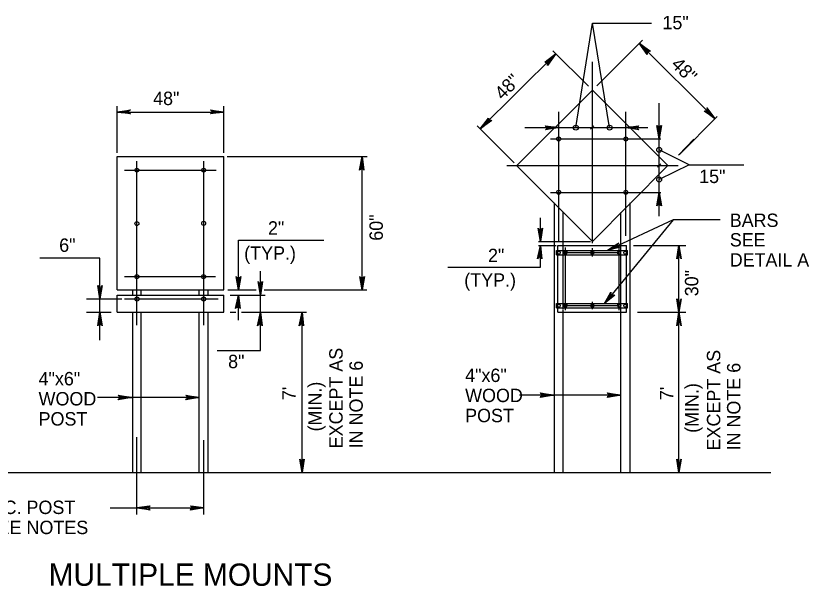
# Model space of a CAD drawing. Extents: x 648590 to 650336, y 294467 to 295061.
# Drawn here: x 648999.2 to 649176.8, y 294775 to 294902.8 of the extents above; entities that cross this region are included whole.
import ezdxf

# ---------------------------------------------------------------- set-up
doc = ezdxf.new("R2010")
doc.units = 0
doc.layers.add('2', color=7, linetype='Continuous')
doc.layers.add('3', color=7, linetype='Continuous')

msp = doc.modelspace()

# ---------------------------------------------------------------- linework, layer by layer
at = {"layer": '2'}
for p, q in [((649124.59, 294877.74), (649128.28, 294901.12)), ((649128.28, 294901.12), (649141.54, 294901.12)), ((649139.51, 294897.35), (649129.28, 294887.12)), ((649155.68, 294879.77), (649138.8, 294896.64)), ((649119.46, 294894.94), (649127.4, 294886.99)), ((649103.18, 294877.47), (649120, 294894.17)), ((649128.28, 294851.87), (649128.28, 294892.49)), ((649111.4, 294869.24), (649128.28, 294886.12)), ((649145.15, 294869.24), (649128.28, 294886.12)), ((649021.91, 294872.12), (649021.91, 294882.56)), ((649045.79, 294872.12), (649045.79, 294882.56)), ((649143.24, 294857.88), (649143.24, 294883.22)), ((649021.91, 294881.22), (649045.79, 294881.22)), ((649120.78, 294852.24), (649120.78, 294881.24)), ((649135.78, 294853.49), (649135.78, 294881.24)), ((649156.26, 294880.23), (649147.78, 294871.75)), ((649110.78, 294869.87), (649102.52, 294878.13)), ((649113.18, 294877.74), (649128.28, 294877.74)), ((649117.15, 294877.74), (649128.28, 294877.74)), ((649127.9, 294877.37), (649128.65, 294878.12)), ((649128.28, 294877.74), (649139.4, 294877.74)), ((649128.28, 294877.74), (649140.67, 294877.74)), ((649118.9, 294875.24), (649143.65, 294875.24)), ((649119.03, 294875.24), (649143.65, 294875.24)), ((649151.03, 294875.12), (649147.58, 294871.59)), ((649021.91, 294841.37), (649021.91, 294871.24)), ((649021.91, 294871.24), (649045.79, 294871.24)), ((649045.79, 294841.37), (649045.79, 294871.24)), ((649046.54, 294871.24), (649077.88, 294871.24)), ((649076.76, 294841.37), (649076.76, 294871.24)), ((649149.98, 294869.42), (649143.24, 294872.77)), ((649026.29, 294833.49), (649026.29, 294870.21)), ((649041.29, 294833.49), (649041.29, 294870.21)), ((649142.87, 294868.87), (649143.62, 294869.62)), ((649149.98, 294869.42), (649143.24, 294866.1)), ((649149.98, 294869.42), (649162.22, 294869.42)), ((649023.54, 294868.24), (649044.04, 294868.24)), ((649026.29, 294868.24), (649026.29, 294868.24)), ((649041.29, 294868.24), (649041.29, 294868.24)), ((649109.15, 294869.24), (649147.53, 294869.24)), ((649109.15, 294869.24), (649147.53, 294869.24)), ((649128.28, 294852.24), (649111.28, 294869.24)), ((649128.28, 294852.24), (649145.15, 294869.24)), ((649118.9, 294863.24), (649143.65, 294863.24)), ((649119.03, 294863.24), (649143.65, 294863.24)), ((649119.78, 294800.49), (649119.78, 294860.87)), ((649136.78, 294800.49), (649136.78, 294860.87)), ((649116.64, 294852.24), (649116.64, 294857.57)), ((649121.78, 294851.87), (649121.78, 294858.74)), ((649134.65, 294851.87), (649134.65, 294858.74)), ((649026.29, 294856.24), (649026.29, 294856.24)), ((649041.29, 294856.24), (649041.29, 294856.24)), ((649049.05, 294841.37), (649049.05, 294852.5)), ((649049.05, 294852.5), (649068.2, 294852.5)), ((649116.22, 294852.24), (649127.9, 294852.24)), ((649121.78, 294836.99), (649121.78, 294851.87)), ((649134.65, 294836.87), (649134.65, 294851.87)), ((649116.25, 294851.37), (649120.15, 294851.37)), ((649116.64, 294846.5), (649116.64, 294851.37)), ((649120.28, 294849.24), (649120.28, 294850.24)), ((649120.28, 294850.24), (649121.37, 294850.24)), ((649120.53, 294836.37), (649120.53, 294851.37)), ((649120.53, 294851.37), (649135.9, 294851.37)), ((649121.37, 294850.24), (649135.28, 294850.24)), ((649122.28, 294836.87), (649122.28, 294850.87)), ((649128.29, 294848.84), (649128.29, 294850.72)), ((649134.28, 294836.87), (649134.28, 294850.87)), ((649135.28, 294850.24), (649136.15, 294850.24)), ((649135.9, 294836.37), (649135.9, 294851.37)), ((649136.15, 294849.24), (649136.15, 294850.24)), ((649137.53, 294851.37), (649149.18, 294851.37)), ((649147.68, 294836.37), (649147.68, 294851.37)), ((649018.04, 294848.5), (649004.59, 294848.5)), ((649018.04, 294839.37), (649018.04, 294848.5)), ((649120.28, 294849.24), (649121.37, 294849.24)), ((649121.37, 294849.24), (649135.28, 294849.24)), ((649122.28, 294849.74), (649134.28, 294849.74)), ((649135.28, 294849.24), (649136.15, 294849.24)), ((649095.96, 294846.5), (649116.64, 294846.5)), ((649053.96, 294840.24), (649053.96, 294845.57)), ((649023.54, 294844.37), (649043.91, 294844.37)), ((649026.29, 294844.37), (649026.29, 294844.37)), ((649041.29, 294844.37), (649041.29, 294844.37)), ((649021.91, 294841.37), (649045.79, 294841.37)), ((649025.41, 294840.24), (649025.41, 294841.37)), ((649027.29, 294840.24), (649027.29, 294841.37)), ((649040.29, 294840.24), (649040.29, 294841.37)), ((649042.29, 294840.24), (649042.29, 294841.37)), ((649046.66, 294841.37), (649053.01, 294841.37)), ((649054.82, 294841.37), (649077.76, 294841.37)), ((649015.04, 294839.37), (649022.91, 294839.37)), ((649018.04, 294830.12), (649018.04, 294839.37)), ((649021.91, 294840.24), (649045.79, 294840.24)), ((649021.91, 294836.37), (649021.91, 294840.24)), ((649023.54, 294839.37), (649044.54, 294839.37)), ((649026.29, 294839.37), (649026.29, 294839.37)), ((649041.29, 294839.37), (649041.29, 294839.37)), ((649045.79, 294836.37), (649045.79, 294840.24)), ((649047.16, 294840.24), (649055.06, 294840.24)), ((649049.05, 294834.61), (649049.05, 294840.24)), ((649053.96, 294827.79), (649053.96, 294840.24)), ((649120.28, 294837.37), (649120.28, 294838.37)), ((649120.28, 294838.37), (649121.37, 294838.37)), ((649121.37, 294838.37), (649135.12, 294838.37)), ((649122.28, 294837.87), (649134.28, 294837.87)), ((649128.29, 294837.09), (649128.29, 294838.75)), ((649135.12, 294838.37), (649136.15, 294838.37)), ((649136.15, 294837.37), (649136.15, 294838.37)), ((649015.04, 294836.37), (649020.54, 294836.37)), ((649021.91, 294836.37), (649045.79, 294836.37)), ((649025.41, 294800.49), (649025.41, 294836.37)), ((649027.29, 294800.49), (649027.29, 294836.37)), ((649040.29, 294800.49), (649040.29, 294836.37)), ((649042.29, 294800.49), (649042.29, 294836.37)), ((649047.16, 294836.37), (649048.44, 294836.37)), ((649049.76, 294836.37), (649064.28, 294836.37)), ((649063.28, 294800.49), (649063.28, 294836.37)), ((649120.28, 294837.37), (649121.37, 294837.37)), ((649120.53, 294836.37), (649135.9, 294836.37)), ((649121.37, 294837.37), (649135.12, 294837.37)), ((649121.78, 294800.49), (649121.78, 294836.87)), ((649134.65, 294800.49), (649134.65, 294836.87)), ((649135.12, 294837.37), (649136.15, 294837.37)), ((649138.4, 294836.37), (649149.18, 294836.37)), ((649147.68, 294800.49), (649147.68, 294836.37)), ((649044.31, 294827.79), (649053.96, 294827.79)), ((649040.29, 294817.29), (649017.48, 294817.29)), ((649134.65, 294817.82), (649111.97, 294817.82)), ((649026.29, 294791.08), (649026.29, 294808.37)), ((649041.29, 294791.08), (649041.29, 294807.74)), ((648903.79, 294800.49), (649168.28, 294800.49)), ((649020.36, 294792.58), (649041.29, 294792.58))]:
    msp.add_line(p, q, dxfattribs=at)
for points in [[(649132.15, 294877.74), (649128.28, 294901.12)], [(649140.55, 294894.39), (649140.68, 294894.64), (649138.8, 294896.64), (649140.55, 294894.39), (649140.55, 294894.14), (649138.8, 294896.64), (649140.8, 294894.77), (649141.05, 294894.89), (649138.8, 294896.64), (649141.3, 294894.89), (649141.05, 294894.89)], [(649117.75, 294892.42), (649117.88, 294892.42), (649120, 294894.17), (649117.75, 294892.42), (649117.63, 294892.42), (649120, 294894.17), (649118.13, 294892.17), (649118.25, 294891.92), (649120, 294894.17), (649118.25, 294891.67), (649118.25, 294891.92)], [(649154.05, 294881.89), (649153.93, 294881.77), (649155.68, 294879.77), (649154.05, 294881.89), (649153.93, 294882.14), (649155.68, 294879.77), (649153.68, 294881.52), (649153.55, 294881.39), (649155.68, 294879.77), (649153.3, 294881.39), (649153.55, 294881.39)], [(649024.66, 294880.97), (649024.66, 294881.1), (649021.91, 294881.22), (649024.66, 294880.97), (649024.91, 294880.85), (649021.91, 294881.22), (649024.54, 294881.47), (649024.66, 294881.6), (649021.91, 294881.22), (649024.91, 294881.72), (649024.66, 294881.6)], [(649042.91, 294881.6), (649043.04, 294881.47), (649045.79, 294881.22), (649042.91, 294881.6), (649042.79, 294881.72), (649045.79, 294881.22), (649043.04, 294881.1), (649042.91, 294880.97), (649045.79, 294881.22), (649042.79, 294880.85), (649042.91, 294880.97)], [(649105.55, 294879.34), (649105.3, 294879.34), (649103.18, 294877.47), (649105.55, 294879.34), (649105.8, 294879.34), (649103.18, 294877.47), (649105.18, 294879.47), (649105.05, 294879.72), (649103.18, 294877.47), (649105.05, 294879.84), (649105.05, 294879.72)], [(649117.89, 294877.99), (649118.02, 294877.87), (649120.77, 294877.74), (649117.89, 294877.99), (649117.77, 294878.12), (649120.77, 294877.74), (649118.02, 294877.62), (649118.02, 294877.49), (649120.77, 294877.74), (649117.77, 294877.24), (649118.02, 294877.49)], [(649138.53, 294877.37), (649138.4, 294877.62), (649135.78, 294877.74), (649138.53, 294877.37), (649138.65, 294877.24), (649135.78, 294877.74), (649138.4, 294877.74), (649138.53, 294877.99), (649135.78, 294877.74), (649138.65, 294878.12), (649138.53, 294877.99)], [(649143.62, 294878.12), (649143.37, 294877.99), (649143.24, 294875.24), (649143.62, 294878.12), (649143.74, 294878.24), (649143.24, 294875.24), (649142.99, 294877.99), (649142.87, 294878.12), (649143.24, 294875.24), (649142.74, 294878.24), (649142.87, 294878.12)], [(649076.38, 294868.37), (649076.51, 294868.49), (649076.76, 294871.24), (649076.38, 294868.37), (649076.13, 294868.24), (649076.76, 294871.24), (649076.88, 294868.49), (649077.01, 294868.37), (649076.76, 294871.24), (649077.13, 294868.24), (649077.01, 294868.37)], [(649142.87, 294860.37), (649142.99, 294860.49), (649143.24, 294863.24), (649142.87, 294860.37), (649142.74, 294860.24), (649143.24, 294863.24), (649143.37, 294860.49), (649143.49, 294860.37), (649143.24, 294863.24), (649143.74, 294860.24), (649143.49, 294860.37)], [(649156.88, 294857.12), (649146.4, 294857.12), (649131.03, 294838.37)], [(649146.4, 294857.12), (649131.65, 294850.24)], [(649116.89, 294854.99), (649116.76, 294854.99), (649116.64, 294852.24), (649116.89, 294854.99), (649117.14, 294855.24), (649116.64, 294852.24), (649116.39, 294854.99), (649116.26, 294854.99), (649116.64, 294852.24), (649116.14, 294855.24), (649116.26, 294854.99)], [(649134.27, 294851.12), (649134.22, 294851.24), (649131.65, 294850.24), (649134.27, 294851.12), (649134.6, 294850.99), (649131.65, 294850.24), (649134.07, 294851.58), (649134.02, 294851.69), (649131.65, 294850.24), (649134.2, 294851.91), (649134.02, 294851.69)], [(649116.26, 294848.62), (649116.39, 294848.62), (649116.64, 294851.37), (649116.26, 294848.62), (649116.01, 294848.37), (649116.64, 294851.37), (649116.76, 294848.62), (649116.89, 294848.62), (649116.64, 294851.37), (649117.01, 294848.37), (649116.89, 294848.62)], [(649147.31, 294848.49), (649147.56, 294848.62), (649147.68, 294851.37), (649147.31, 294848.49), (649147.18, 294848.37), (649147.68, 294851.37), (649147.93, 294848.62), (649148.06, 294848.49), (649147.68, 294851.37), (649148.18, 294848.37), (649148.06, 294848.49)], [(649049.3, 294844.12), (649049.17, 294844.12), (649049.05, 294841.37), (649049.3, 294844.12), (649049.55, 294844.37), (649049.05, 294841.37), (649048.8, 294844.12), (649048.67, 294844.12), (649049.05, 294841.37), (649048.55, 294844.37), (649048.67, 294844.12)], [(649054.21, 294842.99), (649054.08, 294842.99), (649053.96, 294840.24), (649054.21, 294842.99), (649054.46, 294843.24), (649053.96, 294840.24), (649053.71, 294842.99), (649053.58, 294842.99), (649053.96, 294840.24), (649053.46, 294843.24), (649053.58, 294842.99)], [(649077.01, 294844.12), (649076.88, 294844.12), (649076.76, 294841.37), (649077.01, 294844.12), (649077.26, 294844.37), (649076.76, 294841.37), (649076.51, 294844.12), (649076.38, 294844.12), (649076.76, 294841.37), (649076.26, 294844.37), (649076.38, 294844.12)], [(649018.41, 294842.24), (649018.29, 294842.12), (649018.04, 294839.37), (649018.41, 294842.24), (649018.54, 294842.37), (649018.04, 294839.37), (649017.91, 294842.12), (649017.79, 294842.24), (649018.04, 294839.37), (649017.54, 294842.37), (649017.79, 294842.24)], [(649048.67, 294837.49), (649048.8, 294837.49), (649049.05, 294840.24), (649048.67, 294837.49), (649048.42, 294837.24), (649049.05, 294840.24), (649049.17, 294837.49), (649049.3, 294837.49), (649049.05, 294840.24), (649049.42, 294837.24), (649049.3, 294837.49)], [(649148.06, 294839.24), (649147.93, 294839.12), (649147.68, 294836.37), (649148.06, 294839.24), (649148.18, 294839.37), (649147.68, 294836.37), (649147.56, 294839.12), (649147.43, 294839.24), (649147.68, 294836.37), (649147.18, 294839.37), (649147.43, 294839.24)], [(649017.66, 294833.62), (649017.91, 294833.62), (649018.04, 294836.37), (649017.66, 294833.62), (649017.54, 294833.37), (649018.04, 294836.37), (649018.16, 294833.62), (649018.41, 294833.62), (649018.04, 294836.37), (649018.54, 294833.37), (649018.41, 294833.62)], [(649053.58, 294833.62), (649053.71, 294833.62), (649053.96, 294836.37), (649053.58, 294833.62), (649053.33, 294833.37), (649053.96, 294836.37), (649054.08, 294833.62), (649054.21, 294833.62), (649053.96, 294836.37), (649054.33, 294833.37), (649054.21, 294833.62)], [(649062.9, 294833.62), (649063.03, 294833.62), (649063.28, 294836.37), (649062.9, 294833.62), (649062.65, 294833.37), (649063.28, 294836.37), (649063.4, 294833.62), (649063.53, 294833.62), (649063.28, 294836.37), (649063.65, 294833.37), (649063.53, 294833.62)], [(649147.31, 294833.62), (649147.56, 294833.62), (649147.68, 294836.37), (649147.31, 294833.62), (649147.18, 294833.37), (649147.68, 294836.37), (649147.93, 294833.62), (649148.06, 294833.62), (649147.68, 294836.37), (649148.18, 294833.37), (649148.06, 294833.62)], [(649116.77, 294818.2), (649116.89, 294818.07), (649119.64, 294817.82), (649116.77, 294818.2), (649116.64, 294818.32), (649119.64, 294817.82), (649116.89, 294817.7), (649116.77, 294817.57), (649119.64, 294817.82), (649116.64, 294817.32), (649116.77, 294817.57)], [(649131.78, 294818.2), (649131.9, 294818.07), (649134.65, 294817.82), (649131.78, 294818.2), (649131.65, 294818.32), (649134.65, 294817.82), (649131.9, 294817.7), (649131.78, 294817.57), (649134.65, 294817.82), (649131.65, 294817.32), (649131.78, 294817.57)], [(649022.28, 294817.66), (649022.4, 294817.54), (649025.15, 294817.29), (649022.28, 294817.66), (649022.15, 294817.79), (649025.15, 294817.29), (649022.4, 294817.16), (649022.28, 294817.04), (649025.15, 294817.29), (649022.15, 294816.79), (649022.28, 294817.04)], [(649037.41, 294817.66), (649037.54, 294817.54), (649040.29, 294817.29), (649037.41, 294817.66), (649037.29, 294817.79), (649040.29, 294817.29), (649037.54, 294817.16), (649037.41, 294817.04), (649040.29, 294817.29), (649037.29, 294816.79), (649037.41, 294817.04)], [(649063.53, 294803.37), (649063.4, 294803.24), (649063.28, 294800.49), (649063.53, 294803.37), (649063.78, 294803.49), (649063.28, 294800.49), (649063.03, 294803.24), (649062.9, 294803.37), (649063.28, 294800.49), (649062.78, 294803.49), (649062.9, 294803.37)], [(649148.06, 294803.37), (649147.93, 294803.24), (649147.68, 294800.49), (649148.06, 294803.37), (649148.18, 294803.49), (649147.68, 294800.49), (649147.56, 294803.24), (649147.43, 294803.37), (649147.68, 294800.49), (649147.18, 294803.49), (649147.43, 294803.37)], [(649029.16, 294792.21), (649029.04, 294792.46), (649026.29, 294792.58), (649029.16, 294792.21), (649029.29, 294792.08), (649026.29, 294792.58), (649029.04, 294792.83), (649029.16, 294792.96), (649026.29, 294792.58), (649029.29, 294792.96), (649029.16, 294792.96)], [(649038.41, 294792.96), (649038.54, 294792.83), (649041.29, 294792.58), (649038.41, 294792.96), (649038.29, 294792.96), (649041.29, 294792.58), (649038.54, 294792.46), (649038.41, 294792.33), (649041.29, 294792.58), (649038.29, 294792.08), (649038.41, 294792.33)]]:
    msp.add_lwpolyline(points, dxfattribs=at)
for centre, radius in [((649124.59, 294877.74), 0.55), ((649132.15, 294877.74), 0.55), ((649120.75, 294875.21), 0.441), ((649135.78, 294875.19), 0.441), ((649143.24, 294872.77), 0.55), ((649026.31, 294868.21), 0.441), ((649041.26, 294868.21), 0.441), ((649143.24, 294866.1), 0.55), ((649120.75, 294863.26), 0.441), ((649135.78, 294863.25), 0.441), ((649026.31, 294856.24), 0.441), ((649041.26, 294856.31), 0.441), ((649120.76, 294849.74), 0.35), ((649122.28, 294849.74), 0.35), ((649128.27, 294849.74), 0.35), ((649134.25, 294849.74), 0.35), ((649135.68, 294849.74), 0.35), ((649026.31, 294844.35), 0.441), ((649041.23, 294844.35), 0.441), ((649026.33, 294839.34), 0.441), ((649041.25, 294839.34), 0.441), ((649120.76, 294837.87), 0.35), ((649122.28, 294837.87), 0.35), ((649128.29, 294837.87), 0.35), ((649134.28, 294837.87), 0.35), ((649135.67, 294837.87), 0.35)]:
    msp.add_circle(centre, radius, dxfattribs=at)
at = {"layer": '3'}
for p, q in [((649120.78, 294875.24), (649120.78, 294875.24)), ((649120.9, 294875.24), (649120.9, 294875.24)), ((649135.78, 294875.24), (649135.78, 294875.24)), ((649135.78, 294875.24), (649135.78, 294875.24)), ((649120.78, 294863.24), (649120.78, 294863.24)), ((649120.9, 294863.24), (649120.9, 294863.24)), ((649135.78, 294863.24), (649135.78, 294863.24)), ((649135.78, 294863.24), (649135.78, 294863.24))]:
    msp.add_line(p, q, dxfattribs=at)
msp.add_lwpolyline([(649133.03, 294840.24), (649132.78, 294840.24), (649131.03, 294838.37), (649133.03, 294840.24), (649133.28, 294840.24), (649131.03, 294838.37), (649132.53, 294840.49), (649132.4, 294840.74), (649131.03, 294838.37), (649132.4, 294840.87), (649132.4, 294840.74)], dxfattribs=at)

# ---------------------------------------------------------------- texts
at = {"layer": '2'}
msp.add_text('MULTIPLE MOUNTS', height=5, dxfattribs=at).set_placement((649006.55, 294775.11))
at = {"layer": '3'}
for s, height, p in [('15"', 3, (649143.97, 294899.77)), ('48"', 3, (649029.94, 294882.79)), ('15"', 3, (649152.19, 294865.32)), ('BARS', 2.988, (649159.06, 294855.49)), ('2"', 3, (649055.66, 294853.76)), ('SEE', 2.988, (649159.06, 294851.12)), ('6"', 3, (649008.91, 294849.91)), ('(TYP.)', 3, (649050.33, 294848.13)), ('2"', 3, (649104.92, 294847.61)), ('DETAIL A', 2.988, (649159.06, 294846.62)), ('(TYP.)', 3, (649099.6, 294842.1)), ('8"', 3, (649046.73, 294823.86)), ('4"x6"', 3, (649099.8, 294820.76)), ('4"x6"', 3, (649004.3, 294820.01)), ('WOOD', 3, (649004.3, 294815.51)), ('WOOD', 3, (649099.8, 294816.26)), ('POST', 3, (649099.8, 294811.76)), ('POST', 3, (649004.3, 294811.01)), ('C.C. POST', 3, (648992.46, 294791.19)), ('SEE NOTES', 3, (648992.46, 294786.69))]:
    msp.add_text(s, height=height, dxfattribs=at).set_placement(p)
for s, rotation, p in [('48"', 315, (649145.75, 294891.68)), ('48"', 45, (649108.2, 294883.78)), ('60"', 90, (649081.38, 294852.4)), ('30"', 90, (649152.01, 294839.96)), ('EXCEPT AS', 90, (649072.38, 294805.91)), ('EXCEPT AS', 90, (649156.93, 294805.44)), ('IN NOTE 6', 90, (649076.88, 294805.91)), ('IN NOTE 6', 90, (649161.43, 294805.44)), ('(MIN.)', 90, (649067.66, 294809.69)), ('(MIN.)', 90, (649152.05, 294809.37)), ("7'", 90, (649061.86, 294816.7)), ("7'", 90, (649146.41, 294816.7))]:
    msp.add_text(s, height=3, rotation=rotation, dxfattribs=at).set_placement(p)

doc.saveas('drawing.dxf')
